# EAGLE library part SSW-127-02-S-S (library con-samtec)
THROUGH-HOLE .025" SQ POST SOCKET Source: Samtec SSW.pdf
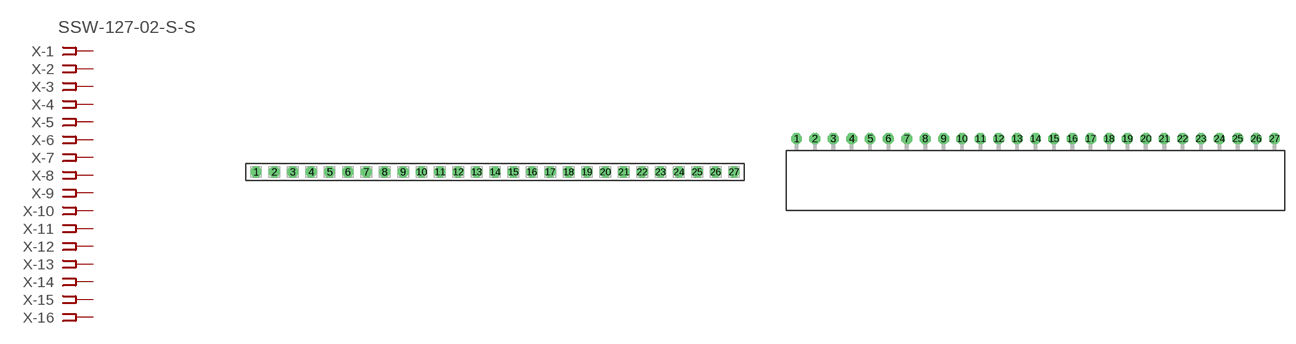
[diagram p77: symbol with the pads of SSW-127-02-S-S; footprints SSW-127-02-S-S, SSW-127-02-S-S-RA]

Designator prefix X; gates -1=FPINV -2=FPIN -3=FPIN -4=FPIN -5=FPIN -6=FPIN -7=FPIN -8=FPIN -9=FPIN -10=FPIN -11=FPIN -12=FPIN -13=FPIN -14=FPIN -15=FPIN -16=FPIN -17=FPIN -18=FPIN -19=FPIN -20=FPIN -21=FPIN -22=FPIN -23=FPIN -24=FPIN -25=FPIN -26=FPIN -27=FPIN

## SSW-127-02-S-S (MPN: SSW-127-02-S-S; OC_FARNELL: unknown; OC_NEWARK: 11P9759)  [SSW-127-02-S-S]
1  -1:1  pas
2  -2:1  pas
3  -3:1  pas
4  -4:1  pas
5  -5:1  pas
6  -6:1  pas
7  -7:1  pas
8  -8:1  pas
9  -9:1  pas
10  -10:1  pas
11  -11:1  pas
12  -12:1  pas
13  -13:1  pas
14  -14:1  pas
15  -15:1  pas
16  -16:1  pas
17  -17:1  pas
18  -18:1  pas
19  -19:1  pas
20  -20:1  pas
21  -21:1  pas
22  -22:1  pas
23  -23:1  pas
24  -24:1  pas
25  -25:1  pas
26  -26:1  pas
27  -27:1  pas

## SSW-127-02-S-S-RA (OC_FARNELL: unknown; OC_NEWARK: unknown)  [SSW-127-02-S-S-RA]
Pads as for SSW-127-02-S-S

## Footprint SSW-127-02-S-S (pad centres in mm)
THROUGH-HOLE .025" SQ POST SOCKET Source: Samtec SSW.pdf
drill 1 pad 1.5 octagon: 1 -33.02,0; 2 -30.48,0; 3 -27.94,0; 4 -25.4,0; 5 -22.86,0; 6 -20.32,0; 7 -17.78,0; 8 -15.24,0; 9 -12.7,0; 10 -10.16,0; 11 -7.62,0; 12 -5.08,0; 13 -2.54,0; 14 0,0; 15 2.54,0; 16 5.08,0; 17 7.62,0; 18 10.16,0; 19 12.7,0; 20 15.24,0; 21 17.78,0; 22 20.32,0; 23 22.86,0; 24 25.4,0; 25 27.94,0; 26 30.48,0; 27 33.02,0

## Footprint SSW-127-02-S-S-RA (pad centres in mm)
THROUGH-HOLE .025" SQ POST SOCKET Source: Samtec SSW.pdf
drill 1 pad 1.5 octagon: 1 -33.02,1.524; 2 -30.48,1.524; 3 -27.94,1.524; 4 -25.4,1.524; 5 -22.86,1.524; 6 -20.32,1.524; 7 -17.78,1.524; 8 -15.24,1.524; 9 -12.7,1.524; 10 -10.16,1.524; 11 -7.62,1.524; 12 -5.08,1.524; 13 -2.54,1.524; 14 0,1.524; 15 2.54,1.524; 16 5.08,1.524; 17 7.62,1.524; 18 10.16,1.524; 19 12.7,1.524; 20 15.24,1.524; 21 17.78,1.524; 22 20.32,1.524; 23 22.86,1.524; 24 25.4,1.524; 25 27.94,1.524; 26 30.48,1.524; 27 33.02,1.524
